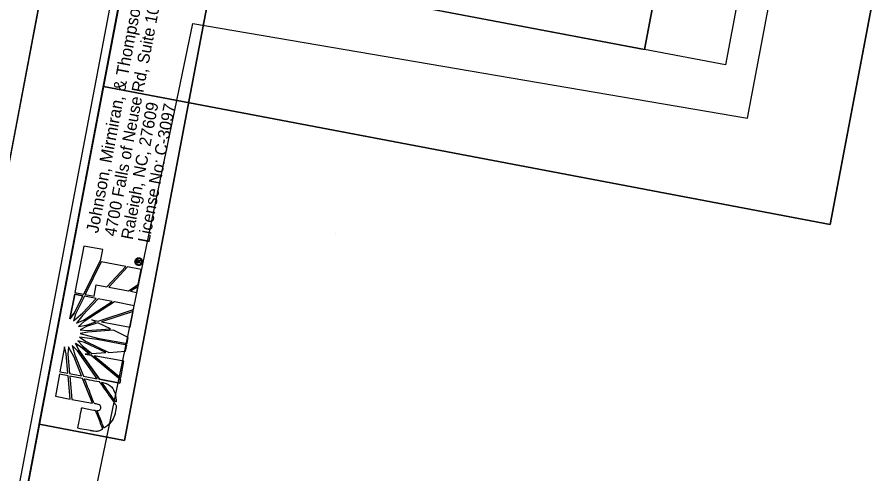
# Model space of a CAD drawing. Extents: x 1615685 to 1617075, y 899072 to 901363.
# Drawn here: x 1615949.1 to 1616192.6, y 900800.2 to 900930.9 of the extents above; entities that cross this region are included whole.
import ezdxf

# ---------------------------------------------------------------- set-up
doc = ezdxf.new("R2010")
doc.units = 0
for name, color, linetype in [('Default', 7, 'Continuous'), ('Exist Plan Preparation Drainage Flow Arrows', 7, 'Continuous'), ('Exist Plan Preparation Drainage Notes Label', 7, 'Continuous'), ('Exist Plan Preparation Watershed Blue', 7, 'Continuous'), ('Exist Structure Minor Pipes CMP 15 Inch Text', 7, 'Continuous'), ('Exist Structure Minor Pipes CMP 24 Inch Text', 7, 'Continuous'), ('Prop Drainage Structure Catch Basin Grate 840 03E CELL', 7, 'Continuous'), ('Prop Drainage Structure Drop Inlet Grate 840 16 CELL', 7, 'Continuous'), ('Prop Drainage Structure Plot Symbol 20 Scale', 7, 'Continuous'), ('Prop Drainage Structure Plot Symbol 50 Scale', 7, 'Continuous'), ('Scratch_Level_8', 7, 'Continuous')]:
    doc.layers.add(name, color=color, linetype=linetype)

msp = doc.modelspace()

# ---------------------------------------------------------------- linework, layer by layer
at = {"layer": 'Default'}
for p, q in [((1615968.12, 900865.41), (1615965.61, 900852.11)), ((1615973.57, 900864.38), (1615968.12, 900865.41)), ((1615973.03, 900861.55), (1615973.57, 900864.38)), ((1615968.12, 900851.64), (1615973.03, 900861.55)), ((1615973.15, 900860.84), (1615968.5, 900851.56)), ((1615980.13, 900859.52), (1615973.15, 900860.84)), ((1615982.8, 900861.15), (1615983, 900861.11)), ((1615983, 900861.11), (1615982.8, 900861.15)), ((1615983.29, 900860.64), (1615983.37, 900861.04)), ((1615984.26, 900860.46), (1615983.29, 900860.64)), ((1615983.37, 900861.04), (1615983.38, 900861.1)), ((1615983.37, 900861.04), (1615983.55, 900861)), ((1615983.55, 900861), (1615983.37, 900861.04)), ((1615983.55, 900861), (1615983.52, 900860.83)), ((1615983.52, 900860.83), (1615983.75, 900860.79)), ((1615983.56, 900861.03), (1615983.55, 900861)), ((1615983.75, 900860.79), (1615983.78, 900860.96)), ((1615983.78, 900860.96), (1615983.78, 900860.97)), ((1615983.78, 900860.96), (1615983.96, 900860.93)), ((1615983.96, 900860.93), (1615983.78, 900860.96)), ((1615983.96, 900860.93), (1615983.92, 900860.75)), ((1615983.92, 900860.75), (1615984.3, 900860.68)), ((1615983.96, 900860.94), (1615983.96, 900860.93)), ((1615984.3, 900860.68), (1615984.26, 900860.46)), ((1615984.71, 900860.79), (1615984.92, 900860.75)), ((1615984.92, 900860.75), (1615984.71, 900860.79)), ((1615984.71, 900860.79), (1615984.71, 900860.79)), ((1615984.93, 900860.75), (1615984.92, 900860.75)), ((1615974.74, 900853.75), (1615980.13, 900859.52)), ((1615980.62, 900859.42), (1615975.26, 900853.65)), ((1615984.54, 900858.68), (1615980.62, 900859.42)), ((1615983.73, 900854.39), (1615984.54, 900858.68)), ((1615971.09, 900851.08), (1615971.7, 900854.32)), ((1615971.7, 900854.32), (1615974.74, 900853.75)), ((1615975.26, 900853.65), (1615980.91, 900852.58)), ((1615980.91, 900852.58), (1615983.73, 900854.39)), ((1615983.61, 900853.77), (1615981.53, 900852.46)), ((1615983.3, 900852.13), (1615983.61, 900853.77)), ((1615965.55, 900851.61), (1615964.19, 900844.61)), ((1615965.36, 900846.22), (1615967.82, 900851.18)), ((1615967.82, 900851.18), (1615965.55, 900851.61)), ((1615965.61, 900852.11), (1615968.05, 900851.65)), ((1615968.3, 900851.09), (1615965.79, 900845.96)), ((1615972.21, 900850.31), (1615967.73, 900845.53)), ((1615967.84, 900846.3), (1615971.64, 900850.42)), ((1615968.05, 900851.65), (1615968.12, 900851.64)), ((1615971.64, 900850.42), (1615968.3, 900851.09)), ((1615968.5, 900851.56), (1615968.54, 900851.56)), ((1615968.54, 900851.56), (1615971.09, 900851.08)), ((1615976.26, 900849.55), (1615972.21, 900850.31)), ((1615981.53, 900852.46), (1615983.3, 900852.13)), ((1615968.02, 900844.21), (1615976.26, 900849.55)), ((1615976.91, 900849.42), (1615968.28, 900843.87)), ((1615982.59, 900848.35), (1615976.91, 900849.42)), ((1615982.38, 900847.23), (1615982.59, 900848.35)), ((1615964.19, 900844.61), (1615965.36, 900846.22)), ((1615965.17, 900844.06), (1615967.84, 900846.3)), ((1615965.79, 900845.96), (1615965.17, 900844.06)), ((1615967.73, 900845.53), (1615966.04, 900843.32)), ((1615972.26, 900843.91), (1615982.38, 900847.23)), ((1615982.25, 900846.72), (1615973.17, 900843.74)), ((1615981.39, 900842.19), (1615982.25, 900846.72)), ((1615966.04, 900843.32), (1615968.02, 900844.21)), ((1615968.28, 900843.87), (1615966.67, 900842.43)), ((1615966.67, 900842.43), (1615968.84, 900842.82)), ((1615968.84, 900842.82), (1615971.61, 900843.7)), ((1615972.17, 900843.42), (1615968.9, 900842.35)), ((1615971.61, 900843.7), (1615970.42, 900844.26)), ((1615970.42, 900844.26), (1615972.26, 900843.91)), ((1615975.82, 900841.69), (1615972.17, 900843.42)), ((1615973.17, 900843.74), (1615981.39, 900842.19)), ((1615968.9, 900842.35), (1615967.06, 900841.43)), ((1615967.06, 900841.43), (1615969.12, 900841.25)), ((1615969.33, 900840.82), (1615967.15, 900840.36)), ((1615967.15, 900840.36), (1615972.08, 900839.1)), ((1615969.12, 900841.25), (1615975.82, 900841.69)), ((1615976.62, 900841.32), (1615969.33, 900840.82)), ((1615980.84, 900839.26), (1615976.62, 900841.32)), ((1615966.47, 900838.33), (1615967.85, 900836.77)), ((1615968.39, 900837.78), (1615966.47, 900838.33)), ((1615971.99, 900838.65), (1615966.95, 900839.32)), ((1615966.95, 900839.32), (1615968.81, 900838.07)), ((1615968.81, 900838.07), (1615975.31, 900835)), ((1615980.43, 900837.06), (1615971.99, 900838.65)), ((1615972.08, 900839.1), (1615980.51, 900837.5)), ((1615980.51, 900837.5), (1615980.84, 900839.26)), ((1615962.67, 900836.55), (1615961.33, 900829.43)), ((1615963.13, 900834.58), (1615962.67, 900836.55)), ((1615963.76, 900836.6), (1615963.62, 900834.49)), ((1615965.39, 900833.58), (1615963.76, 900836.6)), ((1615966.32, 900835.4), (1615964.84, 900836.94)), ((1615964.84, 900836.94), (1615965.61, 900834.3)), ((1615965.74, 900837.53), (1615966.72, 900835.6)), ((1615967.62, 900836.37), (1615965.74, 900837.53)), ((1615966.72, 900835.6), (1615972.67, 900827.29)), ((1615969.78, 900834.59), (1615967.62, 900836.37)), ((1615967.85, 900836.77), (1615970.41, 900834.66)), ((1615974.4, 900834.95), (1615968.39, 900837.78)), ((1615980.1, 900835.32), (1615980.43, 900837.06)), ((1615963.59, 900829.01), (1615963.13, 900834.58)), ((1615963.62, 900834.49), (1615964.08, 900828.91)), ((1615967.5, 900828.27), (1615965.39, 900833.58)), ((1615965.61, 900834.3), (1615968.06, 900828.16)), ((1615972, 900827.42), (1615966.32, 900835.4)), ((1615968.57, 900834.5), (1615969.78, 900834.59)), ((1615970.24, 900834.18), (1615968.57, 900834.5)), ((1615978.61, 900827.25), (1615970.24, 900834.18)), ((1615970.41, 900834.66), (1615974.4, 900834.95)), ((1615979.59, 900832.46), (1615971.15, 900834.01)), ((1615971.15, 900834.01), (1615978.7, 900827.74)), ((1615975.31, 900835), (1615980.1, 900835.32)), ((1615978.7, 900827.74), (1615979.59, 900832.46)), ((1615961.23, 900828.77), (1615960.04, 900822.45)), ((1615963.67, 900828.31), (1615961.23, 900828.77)), ((1615961.33, 900829.43), (1615963.59, 900829.01)), ((1615964.23, 900821.65), (1615963.67, 900828.31)), ((1615964.08, 900828.91), (1615967.5, 900828.27)), ((1615967.8, 900827.53), (1615964.13, 900828.22)), ((1615964.13, 900828.22), (1615964.71, 900821.56)), ((1615968.06, 900828.16), (1615972, 900827.42)), ((1615970.61, 900820.45), (1615967.8, 900827.53)), ((1615972.67, 900827.29), (1615978.41, 900826.21)), ((1615978.41, 900826.21), (1615978.61, 900827.25)), ((1615960.04, 900822.45), (1615964.23, 900821.65)), ((1615964.71, 900821.56), (1615970.61, 900820.45))]:
    msp.add_line(p, q, dxfattribs=at)
for points in [[(1615979.8, 900809.83), (1616005.46, 900944.95), (1615981.08, 900949.57), (1615955.42, 900814.46)], [(1615964.19, 900844.61), (1615965.55, 900851.61), (1615967.82, 900851.18), (1615965.36, 900846.22)], [(1615978.41, 900826.21), (1615972.67, 900827.29), (1615966.72, 900835.6), (1615965.74, 900837.53), (1615967.23, 900836.67), (1615969.78, 900834.59), (1615968.57, 900834.5), (1615970.24, 900834.18), (1615978.61, 900827.25)]]:
    msp.add_lwpolyline(points, close=True, dxfattribs=at)
for points in [[(1615968.12, 900865.41), (1615965.61, 900852.11), (1615968.05, 900851.65), (1615968.12, 900851.64), (1615973.03, 900861.55), (1615973.57, 900864.38), (1615968.12, 900865.41)], [(1615968.5, 900851.56), (1615968.54, 900851.56), (1615971.09, 900851.08), (1615971.7, 900854.32), (1615974.74, 900853.75), (1615980.13, 900859.52), (1615973.15, 900860.84), (1615968.5, 900851.56)], [(1615984.19, 900861.32), (1615984.24, 900861.31), (1615984.28, 900861.31), (1615984.31, 900861.31), (1615984.42, 900861.31), (1615984.38, 900861.11)], [(1615975.26, 900853.65), (1615980.91, 900852.58), (1615983.73, 900854.39), (1615984.54, 900858.68), (1615980.62, 900859.42), (1615975.26, 900853.65), (1615975.26, 900853.65)], [(1615983.3, 900852.13), (1615983.3, 900852.13), (1615983.61, 900853.77), (1615981.53, 900852.46), (1615983.3, 900852.13)], [(1615965.36, 900846.22), (1615967.82, 900851.18), (1615965.55, 900851.61), (1615964.19, 900844.61), (1615965.36, 900846.22)], [(1615965.17, 900844.06), (1615967.84, 900846.3), (1615971.64, 900850.42), (1615968.3, 900851.09), (1615965.79, 900845.96), (1615965.17, 900844.06)], [(1615966.04, 900843.32), (1615968.02, 900844.21), (1615976.26, 900849.55), (1615972.21, 900850.31), (1615967.73, 900845.53), (1615966.04, 900843.32)], [(1615966.67, 900842.43), (1615968.84, 900842.82), (1615971.61, 900843.7), (1615970.42, 900844.26), (1615972.26, 900843.91), (1615982.38, 900847.23), (1615982.59, 900848.35), (1615976.91, 900849.42), (1615968.28, 900843.87), (1615966.67, 900842.43)], [(1615981.39, 900842.19), (1615982.25, 900846.72), (1615973.17, 900843.74), (1615981.39, 900842.19)], [(1615967.06, 900841.43), (1615969.12, 900841.25), (1615975.82, 900841.69), (1615972.17, 900843.42), (1615968.9, 900842.35), (1615967.06, 900841.43)], [(1615967.15, 900840.36), (1615972.08, 900839.1), (1615980.51, 900837.5), (1615980.84, 900839.26), (1615976.62, 900841.32), (1615969.33, 900840.82), (1615967.15, 900840.36)], [(1615966.47, 900838.33), (1615967.85, 900836.77), (1615970.41, 900834.66), (1615974.4, 900834.95), (1615968.39, 900837.78), (1615966.47, 900838.33)], [(1615968.81, 900838.07), (1615975.31, 900835), (1615980.1, 900835.32), (1615980.43, 900837.06), (1615971.99, 900838.65), (1615966.95, 900839.32), (1615968.81, 900838.07)], [(1615963.13, 900834.58), (1615962.67, 900836.55), (1615961.33, 900829.43), (1615963.59, 900829.01), (1615963.13, 900834.58)], [(1615964.08, 900828.91), (1615967.5, 900828.27), (1615965.39, 900833.58), (1615963.76, 900836.6), (1615963.62, 900834.49), (1615964.08, 900828.91)], [(1615968.06, 900828.16), (1615972, 900827.42), (1615966.32, 900835.4), (1615964.84, 900836.94), (1615965.61, 900834.3), (1615968.06, 900828.16)], [(1615965.74, 900837.53), (1615966.72, 900835.6), (1615972.67, 900827.29), (1615978.41, 900826.21), (1615978.61, 900827.25), (1615970.24, 900834.18), (1615968.57, 900834.5), (1615969.78, 900834.59), (1615967.62, 900836.37), (1615965.74, 900837.53)], [(1615978.7, 900827.74), (1615979.59, 900832.46), (1615971.15, 900834.01), (1615978.7, 900827.74)], [(1615964.23, 900821.65), (1615963.67, 900828.31), (1615961.23, 900828.77), (1615960.04, 900822.45), (1615964.23, 900821.65)], [(1615970.61, 900820.45), (1615967.8, 900827.53), (1615964.13, 900828.22), (1615964.71, 900821.56), (1615970.61, 900820.45)]]:
    msp.add_lwpolyline(points, dxfattribs=at)
for points, degree in [([(1615984.92, 900860.75), (1615984.87, 900860.46), (1615984.72, 900860.22), (1615984.46, 900860.05), (1615984.22, 900859.88), (1615983.95, 900859.82), (1615983.65, 900859.88), (1615983.35, 900859.93), (1615983.12, 900860.09), (1615982.96, 900860.33), (1615982.8, 900860.58), (1615982.74, 900860.85), (1615982.8, 900861.15)], 3), ([(1615982.8, 900861.15), (1615982.85, 900861.45), (1615983.01, 900861.68), (1615983.25, 900861.85), (1615983.48, 900862.03), (1615983.76, 900862.09), (1615984.06, 900862.03)], 3), ([(1615983, 900861.11), (1615982.95, 900860.87), (1615983, 900860.65), (1615983.12, 900860.46), (1615983.26, 900860.26), (1615983.45, 900860.13), (1615983.69, 900860.09), (1615983.93, 900860.04), (1615984.15, 900860.09), (1615984.35, 900860.23), (1615984.55, 900860.36), (1615984.67, 900860.55), (1615984.71, 900860.79)], 3), ([(1615984.71, 900860.79), (1615984.76, 900861.03), (1615984.72, 900861.25), (1615984.58, 900861.45), (1615984.45, 900861.65), (1615984.25, 900861.77), (1615984.02, 900861.82), (1615983.78, 900861.86), (1615983.55, 900861.81), (1615983.35, 900861.68), (1615983.16, 900861.54), (1615983.05, 900861.35), (1615983, 900861.11)], 3), ([(1615983.38, 900861.1), (1615983.43, 900861.35), (1615983.55, 900861.45), (1615983.74, 900861.41), (1615983.83, 900861.4), (1615983.89, 900861.35), (1615983.93, 900861.26)], 3), ([(1615983.78, 900860.97), (1615983.81, 900861.11), (1615983.78, 900861.19), (1615983.7, 900861.2), (1615983.63, 900861.22), (1615983.58, 900861.16), (1615983.56, 900861.03)], 3), ([(1615983.93, 900861.26), (1615983.98, 900861.32), (1615984.06, 900861.34), (1615984.19, 900861.32)], 2), ([(1615984.03, 900861.1), (1615984, 900861.07), (1615983.98, 900861.02), (1615983.96, 900860.94)], 2), ([(1615984.38, 900861.11), (1615984.33, 900861.09), (1615984.27, 900861.09), (1615984.2, 900861.1), (1615984.11, 900861.12), (1615984.06, 900861.12), (1615984.03, 900861.1)], 3), ([(1615984.06, 900862.03), (1615984.35, 900861.97), (1615984.59, 900861.82), (1615984.76, 900861.58), (1615984.92, 900861.33), (1615984.98, 900861.05), (1615984.93, 900860.75)], 3), ([(1615972.99, 900819.06), (1615972.92, 900818.68), (1615972.65, 900818.4), (1615971.93, 900818.4), (1615971.93, 900818.4), (1615973.88, 900813.33), (1615973.88, 900813.33), (1615975.61, 900814.45), (1615976.91, 900816.51), (1615977.27, 900818.4), (1615977.36, 900818.89), (1615977.39, 900819.28), (1615977.39, 900819.82), (1615977.39, 900819.82), (1615972.58, 900826.63), (1615972.58, 900826.63), (1615972.58, 900826.63), (1615968.32, 900827.43), (1615968.32, 900827.43), (1615968.32, 900827.43), (1615971.14, 900820.35), (1615971.14, 900820.35), (1615972.74, 900820.05), (1615973.09, 900819.58), (1615972.99, 900819.06)], 3), ([(1615972.99, 900819.06), (1615972.92, 900818.68), (1615972.65, 900818.4), (1615971.93, 900818.4), (1615971.93, 900818.4), (1615973.88, 900813.33), (1615973.88, 900813.33), (1615975.61, 900814.45), (1615976.91, 900816.51), (1615977.27, 900818.4), (1615977.36, 900818.89), (1615977.39, 900819.28), (1615977.39, 900819.82), (1615977.39, 900819.82), (1615972.58, 900826.63), (1615972.58, 900826.63), (1615972.58, 900826.63), (1615968.32, 900827.43), (1615968.32, 900827.43), (1615968.32, 900827.43), (1615971.14, 900820.35), (1615971.14, 900820.35), (1615972.74, 900820.05), (1615973.09, 900819.58), (1615972.99, 900819.06)], 3), ([(1615973.24, 900826.5), (1615973.24, 900826.5), (1615977.4, 900820.62), (1615977.4, 900820.62), (1615977.26, 900823.14), (1615976.11, 900825.84), (1615973.24, 900826.5)], 3), ([(1615967.55, 900819.15), (1615967.55, 900819.15), (1615966.45, 900813.29), (1615966.45, 900813.29), (1615966.45, 900813.29), (1615970.11, 900812.6), (1615970.11, 900812.6), (1615970.11, 900812.6), (1615970.5, 900812.53), (1615970.5, 900812.53), (1615971.64, 900812.31), (1615972.62, 900812.51), (1615973.51, 900813.04), (1615973.51, 900813.04), (1615971.5, 900818.4), (1615971.42, 900818.42), (1615971.42, 900818.42), (1615967.55, 900819.15), (1615967.55, 900819.15)], 3)]:
    msp.add_open_spline(points, degree=degree, dxfattribs=at)
at = {"layer": 'Exist Plan Preparation Drainage Flow Arrows'}
msp.add_lwpolyline([(1616744, 899325.3), (1617054.75, 900962.05), (1616018.28, 901158.86), (1615707.51, 899522.1)], close=True, dxfattribs=at)
at = {"layer": 'Exist Plan Preparation Drainage Notes Label'}
msp.add_lwpolyline([(1616761.22, 899308.8), (1617075.25, 900962.75), (1615999.47, 901167.01), (1615685.44, 899513.06)], close=True, dxfattribs=at)
at = {"layer": 'Exist Plan Preparation Watershed Blue'}
msp.add_lwpolyline([(1615955.42, 900814.46), (1615981.06, 900949.58), (1616005.46, 900944.95), (1615979.82, 900809.83)], close=True, dxfattribs=at)
at = {"layer": 'Exist Structure Minor Pipes CMP 15 Inch Text'}
for p, q in [((1616128.49, 900921.6), (1616165.81, 901118.12)), ((1616128.49, 900921.6), (1616165.81, 901118.12)), ((1616188.9, 901113.74), (1616151.58, 900917.21)), ((1616188.9, 901113.74), (1616151.58, 900917.21)), ((1616151.58, 900917.21), (1616128.49, 900921.6)), ((1616151.58, 900917.21), (1616128.49, 900921.6))]:
    msp.add_line(p, q, dxfattribs=at)
at = {"layer": 'Exist Structure Minor Pipes CMP 24 Inch Text'}
msp.add_line((1615999.47, 901167.01), (1615685.44, 899513.06), dxfattribs=at)
at = {"layer": 'Prop Drainage Structure Catch Basin Grate 840 03E CELL'}
msp.add_lwpolyline([(1616779.49, 899525.69), (1617040.64, 900901.13), (1616216.84, 901057.54), (1616181.54, 900871.6), (1615973.76, 900911.05), (1615747.91, 899721.55)], close=True, dxfattribs=at)
at = {"layer": 'Prop Drainage Structure Drop Inlet Grate 840 16 CELL'}
for points in [[(1616181.54, 900871.6), (1616226.17, 901106.67), (1616018.4, 901146.15), (1615973.76, 900911.05)], [(1615738.61, 899672.4), (1616770.16, 899476.57), (1617049.96, 900950.24), (1616226.17, 901106.65), (1616181.54, 900871.6), (1615973.76, 900911.05)]]:
    msp.add_lwpolyline(points, close=True, dxfattribs=at)
at = {"layer": 'Prop Drainage Structure Plot Symbol 20 Scale'}
msp.add_lwpolyline([(1616187.49, 901058.27), (1617032.97, 900874.07), (1617012.18, 900781.12), (1616950.6, 900773.34), (1616752.73, 900760.58), (1616722.43, 900593.62), (1616951.14, 900496.73), (1616753.23, 899510.43), (1615915.8, 899646.19), (1615751.76, 899738.03), (1615999.36, 900929.08), (1616157.93, 900902)], close=True, dxfattribs=at)
at = {"layer": 'Prop Drainage Structure Plot Symbol 50 Scale'}
msp.add_line((1616040.03, 900869.1), (1616040.03, 900869.1), dxfattribs=at)
at = {"layer": 'Scratch_Level_8'}
for points in [[(1616018.4, 901146.14), (1615738.59, 899672.43), (1616770.16, 899476.57), (1617049.96, 900950.25)], [(1616770.16, 899476.57), (1615738.61, 899672.4), (1615981.06, 900949.58), (1616128.49, 900921.6), (1616165.82, 901118.12), (1617049.96, 900950.25)], [(1616017.98, 900942.57), (1616036.64, 901040.86), (1616147.18, 901019.87), (1616128.49, 900921.6)]]:
    msp.add_lwpolyline(points, close=True, dxfattribs=at)

# ---------------------------------------------------------------- texts
at = {"layer": 'Default'}
for s, height, p in [('Johnson, Mirmiran, & Thompson Inc.', 3.5139, (1615972.23, 900868.92)), ('4700 Falls of Neuse Rd, Suite 100, ', 3.4135, (1615977.3, 900867.96)), ('Raleigh, NC, 27609', 3.4135, (1615982.09, 900867.05)), ('License No: C-3097', 3.4135, (1615986.88, 900866.14))]:
    msp.add_text(s, height=height, rotation=79.2488, dxfattribs=at).set_placement(p)

doc.saveas('drawing.dxf')
